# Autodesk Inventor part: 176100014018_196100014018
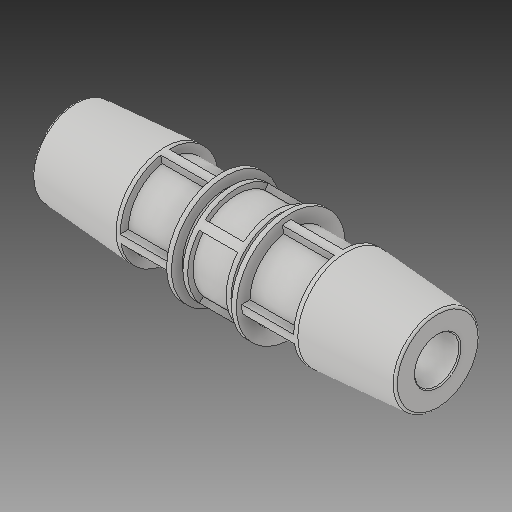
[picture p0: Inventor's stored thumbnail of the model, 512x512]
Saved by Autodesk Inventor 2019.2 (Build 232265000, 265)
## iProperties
Created: 2016-12
Part Number: 176100014018_196100014018
Material: Generic
Description: PLASSON UNIVERSAL SLIP REPAIR COUPLER 19-22 SERIES 17
Document SubType Name: Modeling
Designer: KIM
Mass: 1150.9 g
Surface Area: 2070.91 cm^2
Volume: 1150.9 cm^3
Density: 1 g/cm^3
Appearance: Default
Author: KIM
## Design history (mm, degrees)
derived "17610.ipt"
feature "Solid1::17610.ipt"
tag "TaggingFeature1"
body "Solid1"
other parameters: "d5" = 119, "d11" = 29.75, "d12" = 2.38, "d14" = 45, "d15" = 22, "d16" = 21.56, "d17" = 43.2, "d20" = 40.5, "d21" = 80 deg, "d22" = 25.71429, "d23" = 0, "d25" = 360 deg, "d31" = 23.8, "d32" = 48.6, "d33" = 80 deg, "d34" = 40 deg, "d35" = 43.2, "d36" = 9.52, "d37" = 0, "d39" = 360 deg, "d48" = 1.1, "d52" = 0.54, "d55" = 54, "d58" = 48.6, "d_" = 22, "E_" = 54, "l_" = 119
